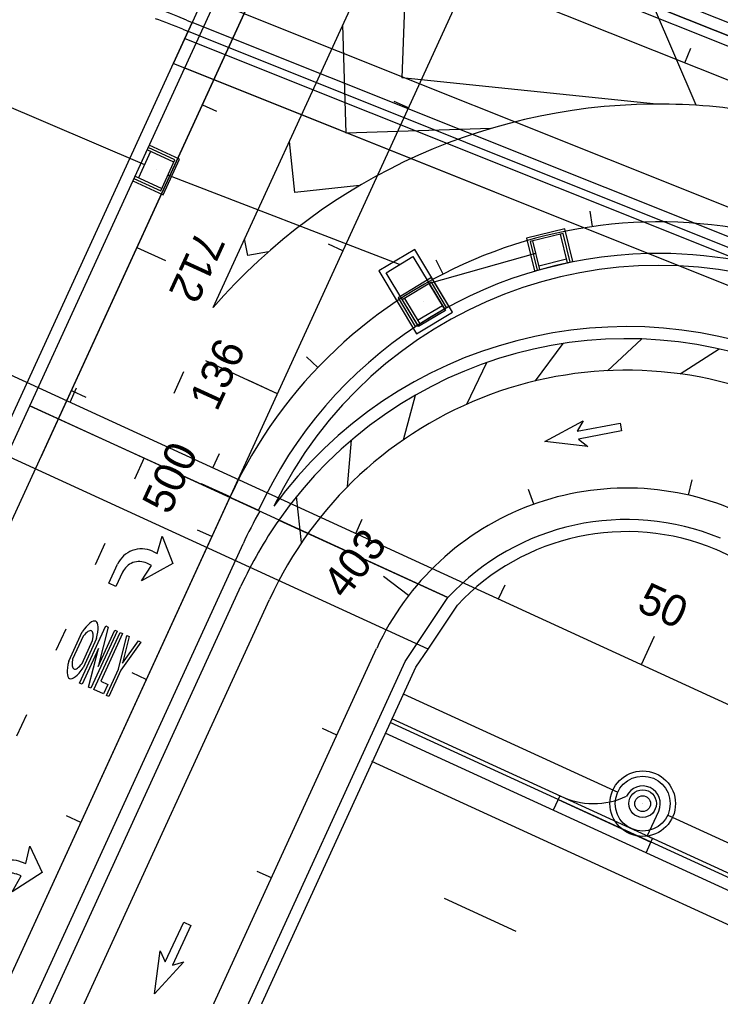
# Model space of a CAD drawing. Extents: x 468143 to 491361, y 1438528 to 1468730.
# Drawn here: x 487920.8 to 488010, y 1467075.2 to 1467199.5 of the extents above; entities that cross this region are included whole.
import ezdxf

# ---------------------------------------------------------------- set-up
doc = ezdxf.new("R2010")
doc.units = 0
doc.layers.add('Default', color=7, linetype='Continuous')
doc.layers.add('Xreference_dp', color=7, linetype='Continuous')

# ---------------------------------------------------------------- blocks, each defined once
blk = doc.blocks.new('POINT_DISPLAY')
at = {"layer": 'Default'}
blk.add_line((0, 0), (0, 0), dxfattribs=at)
blk = doc.blocks.new('InltCurb1_35')
at = {"layer": 'Default'}
for p, q in [((2.25, 2), (2.25, 5.5)), ((-10, 2), (-10, 0)), ((-10, 1.5), (3, 1.5)), ((3, 2), (2.25, 2)), ((3, 0), (3, 2))]:
    blk.add_line(p, q, dxfattribs=at)
for radius in [1.75, 1]:
    blk.add_circle((0, 5.5), radius, dxfattribs=at)
for centre, radius, start, end in [((0, 5.5), 2.25, 0, 180), ((-9.85, 12), 10, 269.1432, 319.4677)]:
    blk.add_arc(centre, radius, start, end, dxfattribs=at)
for p in [(0, 7.75), (-1.22, 6.76), (-0.66, 7.12), (0, 7.25), (0, 7.25), (0.7, 7.1), (1.26, 6.72), (-1.75, 5.5), (-1.75, 5.5), (-1.6, 6.2), (0, 5.5), (0, 5.5), (1.62, 6.16), (1.75, 5.5), (1.75, 5.5), (-1.62, 4.84), (-1.26, 4.28), (-0.7, 3.9), (0, 3.75), (0, 3.75), (0.66, 3.88), (1.22, 4.24), (1.6, 4.8), (0, 0), (0, 0)]:
    blk.add_blockref('POINT_DISPLAY', p, dxfattribs=at)
blk = doc.blocks.new('JBottom70Dia')
at = {"layer": 'Default'}
for radius in [4.17, 3.5, 3.5]:
    blk.add_circle((0, 0), radius, dxfattribs=at)
for p in [(-2.44, 2.51), (-1.32, 3.24), (0, 3.5), (0, 3.5), (0, 3.5), (1.41, 3.2), (-3.2, 1.41), (2.51, 2.44), (3.24, 1.32), (-3.5, 0), (-3.5, 0), (0, 0), (0, 0), (0, 0), (3.5, 0), (3.5, 0), (-3.24, -1.32), (-2.51, -2.44), (3.2, -1.41), (-1.41, -3.2), (0, -3.5), (0, -3.5), (0, -3.5), (1.32, -3.24), (2.44, -2.51)]:
    blk.add_blockref('POINT_DISPLAY', p, dxfattribs=at)
blk = doc.blocks.new('JBottom40x80_8')
at = {"layer": 'Default'}
for p, q in [((2.67, 4.67), (-2.67, 4.67)), ((-2.67, 4.67), (-2.67, -4.67)), ((-2, -4), (-2, 4)), ((-2, 4), (2, 4)), ((2, 4), (2, -4)), ((2.67, -4.67), (2.67, 4.67)), ((-2.67, -4.67), (2.67, -4.67)), ((2, -4), (-2, -4))]:
    blk.add_line(p, q, dxfattribs=at)
for p in [(-2, 4), (0, 4), (0, 4), (0, 4), (2, 4), (0, 0), (0, 0), (0, 0), (-2, 0), (-2, 0), (2, 0), (2, 0), (-2, -4), (0, -4), (0, -4), (0, -4), (2, -4)]:
    blk.add_blockref('POINT_DISPLAY', p, dxfattribs=at)
blk = doc.blocks.new('DAMerge_2')
at = {"layer": 'Default'}
blk.add_lwpolyline([(0.71, -4.09), (0, -3.39), (3.95, 0.56), (2.42, 0.68), (7.31, 3.21), (4.77, -1.68), (4.66, -0.15), (0.71, -4.09)], dxfattribs=at)
blk = doc.blocks.new('DALeftTurn_4_1')
at = {"layer": 'Default'}
for points in [[(5.67, 3.17), (2, 0.5), (4.33, 0.83), (4.33, 0.17)], [(6, 0.17), (6, 0.83), (8.25, 0.5), (5.67, 3.17)], [(2, -2.17), (0, -2.17), (0, -3.17), (2.67, -3.17)]]:
    blk.add_lwpolyline(points, dxfattribs=at)
for centre, radius in [((2, 0.17), 2.33), ((2.67, 0.17), 3.33)]:
    blk.add_arc(centre, radius, 270, 0, dxfattribs=at)
blk = doc.blocks.new('BikeONLY_3')
at = {"layer": 'Default'}
for p, q in [((0.97, 1.833), (3.03, 1.833)), ((2.8, 1.667), (1.2, 1.667)), ((3.03, 0.833), (0.97, 0.833)), ((1.2, 1), (2.8, 1))]:
    blk.add_line(p, q, dxfattribs=at)
for points in [[(0, -0.167), (0, 0), (2.5, 0.458), (0, 0.458), (0, 0.625), (4, 0.625), (4, 0.458), (1.45, 0), (4, 0), (4, -0.167), (0, -0.167)], [(0, -1.042), (0, -0.375), (4, -0.375), (4, -0.542), (0.667, -0.542), (0.667, -1.042), (0, -1.042)], [(4, -1.833), (1.833, -1.417), (0, -1.417), (0, -1.25), (1.833, -1.25), (4, -0.833), (4, -1.003), (2.283, -1.333), (4, -1.664), (4, -1.833)]]:
    blk.add_lwpolyline(points, dxfattribs=at)
for major_axis, ratio, start_param, end_param in [((2, 0), 0.291667, 2.111896, 4.171289), ((1.333, 0), 0.3125, 2.214297, 4.068888), ((1.333, 0), 0.3125, 5.35589, 7.210481), ((2, 0), 0.291667, 5.253489, 7.312882)]:
    blk.add_ellipse((2, 1.333), major_axis=major_axis, ratio=ratio, start_param=start_param, end_param=end_param, dxfattribs=at)
blk = doc.blocks.new('DARightTurn_4')
at = {"layer": 'Default'}
for points in [[(2, 2.17), (0, 2.17), (0, 3.17), (2.67, 3.17)], [(5.67, -3.17), (2, -0.5), (4.33, -0.83), (4.33, -0.17)], [(6, -0.17), (6, -0.83), (8.25, -0.5), (5.67, -3.17)]]:
    blk.add_lwpolyline(points, dxfattribs=at)
for centre, radius in [((2.67, -0.17), 3.33), ((2, -0.17), 2.33)]:
    blk.add_arc(centre, radius, 360, 90, dxfattribs=at)
blk = doc.blocks.new('DAMerge_6')
at = {"layer": 'Default'}
blk.add_lwpolyline([(0.71, -4.09), (0, -3.39), (3.95, 0.56), (2.42, 0.68), (7.31, 3.21), (4.77, -1.68), (4.66, -0.15), (0.71, -4.09)], dxfattribs=at)
blk = doc.blocks.new('DALeftTurn_5')
at = {"layer": 'Default'}
for points in [[(5.67, 3.17), (2, 0.5), (4.33, 0.83), (4.33, 0.17)], [(6, 0.17), (6, 0.83), (8.25, 0.5), (5.67, 3.17)], [(2, -2.17), (0, -2.17), (0, -3.17), (2.67, -3.17)]]:
    blk.add_lwpolyline(points, dxfattribs=at)
for centre, radius in [((2, 0.17), 2.33), ((2.67, 0.17), 3.33)]:
    blk.add_arc(centre, radius, 270, 0, dxfattribs=at)

msp = doc.modelspace()

# ---------------------------------------------------------------- linework, layer by layer
at = {"layer": 'Xreference_dp'}
for p, q in [((487372.29, 1467405.61), (488386.67, 1466939.92)), ((487859.77, 1466947.15), (487993.45, 1467238.69)), ((487859.77, 1466947.15), (487993.45, 1467238.69)), ((487965.18, 1467234.63), (487923.5, 1467143.73)), ((487945.48, 1467162.86), (487976.83, 1467231.24)), ((487856.07, 1466996.67), (487960.96, 1467225.43)), ((487940.43, 1467193.93), (487954.61, 1467224.87)), ((487941.86, 1467193.36), (487956.05, 1467224.3)), ((488054.01, 1467178.92), (487952.21, 1467219.64)), ((487970.43, 1467217.28), (487969.51, 1467192.12)), ((487948.97, 1467216.63), (488191.23, 1467119.72)), ((487936.77, 1467181.05), (487859.2, 1467214.13)), ((488074.17, 1467173.86), (487977.62, 1467212.48)), ((488073.59, 1467172.43), (487975.55, 1467211.65)), ((487977.21, 1467210.99), (488073.48, 1467172.48)), ((487943.4, 1467202.7), (488185.65, 1467105.79)), ((488006.95, 1467188.61), (488001.53, 1467201.26)), ((487941.99, 1467197.34), (487942.83, 1467199.16)), ((487942.1, 1467199.46), (487942.83, 1467199.16)), ((488045.62, 1467158.04), (487942.83, 1467199.16)), ((487917.83, 1467144.65), (487942.3, 1467198.03)), ((487941.63, 1467198.29), (487942.36, 1467198)), ((487942.3, 1467198.03), (488042.37, 1467157.99)), ((487941.89, 1467197.12), (488041.54, 1467157.25)), ((488005.53, 1467194), (488006.28, 1467195.86)), ((487940.43, 1467193.93), (488040.24, 1467154)), ((487922.15, 1467150.37), (487941.86, 1467193.36)), ((487941.86, 1467193.36), (488000.88, 1467169.75)), ((488001.92, 1467188.76), (487969.51, 1467192.12)), ((487944.11, 1467188.68), (487945.93, 1467187.85)), ((487970.33, 1467188.27), (487968.51, 1467189.1)), ((487937.35, 1467183.53), (487935.27, 1467178.99)), ((487941.22, 1467181.76), (487937.35, 1467183.53)), ((487937.53, 1467182.72), (487936, 1467179.39)), ((487940.48, 1467181.37), (487937.07, 1467182.93)), ((487940.62, 1467181.67), (487937.21, 1467183.23)), ((487938.82, 1467177.73), (487940.62, 1467181.67)), ((487939.13, 1467177.22), (487941.22, 1467181.76)), ((487935.27, 1467178.99), (487939.13, 1467177.22)), ((487935.41, 1467179.29), (487938.82, 1467177.73)), ((487935.55, 1467179.6), (487938.96, 1467178.03)), ((487969.2, 1467168.33), (487939.72, 1467179.7)), ((487993.75, 1467173.17), (487993.46, 1467175.15)), ((487990.23, 1467172.87), (487985.37, 1467171.68)), ((487991.24, 1467168.74), (487990.23, 1467172.87)), ((487985.37, 1467171.68), (487986.38, 1467167.55)), ((487990.02, 1467172.3), (487985.81, 1467171.27)), ((487985.81, 1467171.27), (487986.71, 1467167.63)), ((487986.14, 1467171.35), (487987.03, 1467167.71)), ((487990.59, 1467168.58), (487989.7, 1467172.22)), ((487990.92, 1467168.66), (487990.02, 1467172.3)), ((487935.78, 1467170.5), (487939.41, 1467168.84)), ((487961.99, 1467170.09), (487960.17, 1467170.92)), ((487986.52, 1467169.77), (487972.98, 1467165.93)), ((487986.52, 1467169.77), (487972.98, 1467165.93)), ((487974.77, 1467167.14), (487973.86, 1467168.92)), ((487986.38, 1467167.55), (487991.24, 1467168.74)), ((487986.91, 1467168.19), (487990.47, 1467169.07)), ((487973.29, 1467166.7), (487969.01, 1467164.12)), ((487973.26, 1467166.1), (487969.55, 1467163.87)), ((487975.19, 1467162.88), (487973.26, 1467166.1)), ((487975.48, 1467163.06), (487973.29, 1467166.7)), ((487974.91, 1467162.71), (487972.98, 1467165.93)), ((487969.01, 1467164.12), (487971.19, 1467160.48)), ((487969.55, 1467163.87), (487971.48, 1467160.65)), ((487969.83, 1467164.04), (487971.77, 1467160.82)), ((487971.19, 1467160.48), (487975.48, 1467163.06)), ((487971.51, 1467161.25), (487974.65, 1467163.14)), ((487995.66, 1467154.84), (487999.98, 1467158.87)), ((487986.51, 1467153.54), (487990.01, 1467158.29)), ((488004.9, 1467154.44), (488009.89, 1467157.6)), ((487958.81, 1467155.24), (487957.37, 1467156.62)), ((487953.66, 1467151.91), (487944.57, 1467156.08)), ((487977.75, 1467150.57), (487980.32, 1467155.89)), ((487941.72, 1467154.68), (487940.47, 1467151.95)), ((487927.27, 1467150.82), (487928.11, 1467152.64)), ((487953.66, 1467151.91), (487950.02, 1467153.58)), ((487927.44, 1467152.32), (487929.26, 1467151.49)), ((487969.69, 1467146.04), (487971.24, 1467151.74)), ((487849.18, 1466991.24), (487922.15, 1467150.37)), ((487975.36, 1467125.97), (487922.15, 1467150.37)), ((487922.15, 1467150.37), (487951.27, 1467137.1)), ((487962.6, 1467140.11), (487963.07, 1467145.99)), ((487972.84, 1467119.42), (487917.83, 1467144.65)), ((487936.72, 1467143.77), (487935.47, 1467141.04)), ((487945.45, 1467142.48), (487946.28, 1467144.3)), ((487947.63, 1467138.77), (487943.99, 1467140.44)), ((488005.98, 1467139.01), (488006.43, 1467140.95)), ((487859.77, 1466947.15), (487947.63, 1467138.77)), ((487956.73, 1467132.97), (487956.1, 1467138.84)), ((487986.29, 1467137.85), (487985.61, 1467139.73)), ((487953.84, 1467135.83), (487975.36, 1467125.97)), ((487963.63, 1467134.13), (487964.46, 1467135.95)), ((487945.32, 1467133.73), (487943.5, 1467134.56)), ((487878.29, 1466977.96), (487949.29, 1467132.79)), ((487931.72, 1467132.86), (487930.47, 1467130.14)), ((488009.46, 1467132.11), (488535.31, 1466889.3)), ((487970.35, 1467126.22), (487967.18, 1467128.65)), ((487981.8, 1467125.79), (487982.64, 1467127.61)), ((487880.11, 1466977.12), (487949.02, 1467127.41)), ((487883.23, 1466974.33), (487952.66, 1467125.74)), ((487969.93, 1467117.82), (487975.36, 1467125.97)), ((487972.84, 1467119.42), (487976.58, 1467125.01)), ((487926.72, 1467121.96), (487925.47, 1467119.23)), ((487999.98, 1467117.44), (488001.65, 1467121.08)), ((487896.86, 1466968.07), (487966.29, 1467119.49)), ((487896.86, 1466968.07), (487966.29, 1467119.49)), ((487971.29, 1467117.1), (487972.84, 1467119.42)), ((487903.94, 1466973.9), (487969.93, 1467117.82)), ((487905.34, 1466973.26), (487971.29, 1467117.1)), ((487936.98, 1467115.55), (487935.17, 1467116.39)), ((487969.68, 1467113.72), (487996.97, 1467101.21)), ((487921.72, 1467111.05), (487920.47, 1467108.32)), ((488379.42, 1466921.99), (487968.21, 1467110.55)), ((487961.24, 1467108.47), (487959.42, 1467109.3)), ((488379.21, 1466921.54), (487968, 1467110.09)), ((488378.58, 1466920.18), (487967.36, 1467108.73)), ((488376.92, 1466916.54), (487965.68, 1467105.11)), ((487928.65, 1467097.37), (487926.83, 1467098.21)), ((488003.33, 1467098.29), (488087.86, 1467059.53)), ((487952.9, 1467090.29), (487951.08, 1467091.12)), ((487984.03, 1467083.49), (487974.94, 1467087.66))]:
    msp.add_line(p, q, dxfattribs=at)
for points in [[(487980.83, 1467185.66), (487962.43, 1467185.05), (487961.97, 1467198.84)], [(487964.11, 1467178.39), (487955.88, 1467177.5), (487955.18, 1467184.02)], [(487952.53, 1467169.98), (487949.89, 1467169.49), (487949.49, 1467171.63)]]:
    msp.add_lwpolyline(points, dxfattribs=at)
for centre, radius, start, end in [((487523.34, 1466152.69), 1127.42, 68.1961, 69.14997), ((487416.74, 1465829.61), 1465.88, 69.01753, 69.16453), ((488002.17, 1467113.76), 75, 88.9711, 139.1069), ((488002.17, 1467113.76), 75, 68.1341, 88.9711), ((488002.17, 1467113.76), 60, 68.1961, 155.3671), ((488002.17, 1467113.76), 60, 68.1961, 155.3671), ((488002.17, 1467113.76), 56, 91.3222, 155.3671), ((488002.17, 1467113.76), 56, 68.1961, 91.3222), ((488002.17, 1467113.76), 54.46, 68.1961, 154.058), ((487998.11, 1467104.9), 55.54, 65.2153, 143.9544), ((487998.11, 1467104.9), 54, 65.2153, 145.0537), ((487998.11, 1467104.9), 50, 65.2153, 155.3671), ((487998.11, 1467104.9), 50, 65.2153, 155.3671), ((487998.11, 1467104.9), 35, 65.2153, 155.3671), ((487998.11, 1467104.9), 35, 65.2153, 155.3671), ((488000.19, 1467109.45), 56, 150.5858, 155.3671), ((487998.11, 1467104.9), 54, 145.0537, 155.3671), ((487998.11, 1467104.9), 31, 67.3625, 137.1956), ((487998.11, 1467104.9), 29.46, 67.3625, 136.9606)]:
    msp.add_arc(centre, radius, start, end, dxfattribs=at)

# ---------------------------------------------------------------- block references
for name, p, rotation in [('POINT_DISPLAY', (487937.53, 1467182.72), 65.36711903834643), ('POINT_DISPLAY', (487936.31, 1467181.26), 65.36711903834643), ('POINT_DISPLAY', (487936.31, 1467181.26), 65.36711903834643), ('POINT_DISPLAY', (487936.77, 1467181.05), 65.36711903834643), ('POINT_DISPLAY', (487936.77, 1467181.05), 65.36711903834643), ('POINT_DISPLAY', (487939.01, 1467182.04), 65.36711903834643), ('POINT_DISPLAY', (487939.01, 1467182.04), 65.36711903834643), ('POINT_DISPLAY', (487940.48, 1467181.37), 65.36711903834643), ('POINT_DISPLAY', (487938.24, 1467180.38), 65.36711903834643), ('POINT_DISPLAY', (487938.24, 1467180.38), 65.36711903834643), ('POINT_DISPLAY', (487936, 1467179.39), 65.36711903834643), ('POINT_DISPLAY', (487937.48, 1467178.71), 65.36711903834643), ('POINT_DISPLAY', (487937.48, 1467178.71), 65.36711903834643), ('POINT_DISPLAY', (487939.72, 1467179.7), 65.36711903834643), ('POINT_DISPLAY', (487939.72, 1467179.7), 65.36711903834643), ('POINT_DISPLAY', (487940.17, 1467179.49), 65.36711903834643), ('POINT_DISPLAY', (487938.96, 1467178.03), 65.36711903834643), ('POINT_DISPLAY', (487986.14, 1467171.35), -166.19908272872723), ('POINT_DISPLAY', (487987.8, 1467172.27), -166.19908272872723), ('POINT_DISPLAY', (487987.92, 1467171.79), -166.19908272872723), ('POINT_DISPLAY', (487987.92, 1467171.79), -166.19908272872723), ('POINT_DISPLAY', (487989.7, 1467172.22), -166.19908272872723), ('JBottom40x80_8', (487971.26, 1467164.9), -149.01034887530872), ('POINT_DISPLAY', (487988.3, 1467170.21), -166.19908272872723), ('POINT_DISPLAY', (487988.3, 1467170.21), -166.19908272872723), ('POINT_DISPLAY', (487990.08, 1467170.65), -166.19908272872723), ('POINT_DISPLAY', (487990.08, 1467170.65), -166.19908272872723), ('POINT_DISPLAY', (487986.52, 1467169.77), -166.19908272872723), ('POINT_DISPLAY', (487986.52, 1467169.77), -166.19908272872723), ('POINT_DISPLAY', (487988.69, 1467168.63), -166.19908272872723), ('POINT_DISPLAY', (487988.69, 1467168.63), -166.19908272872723), ('POINT_DISPLAY', (487990.47, 1467169.07), -166.19908272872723), ('POINT_DISPLAY', (487986.91, 1467168.19), -166.19908272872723), ('POINT_DISPLAY', (487988.81, 1467168.15), -166.19908272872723), ('POINT_DISPLAY', (487988.81, 1467168.15), -166.19908272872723), ('POINT_DISPLAY', (487971.15, 1467165.41), -149.01034887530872), ('POINT_DISPLAY', (487971.41, 1467164.98), -149.01034887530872), ('POINT_DISPLAY', (487971.41, 1467164.98), -149.01034887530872), ('POINT_DISPLAY', (487972.98, 1467165.93), -149.01034887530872), ('POINT_DISPLAY', (487969.83, 1467164.04), -149.01034887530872), ('POINT_DISPLAY', (487973.81, 1467164.53), -149.01034887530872), ('POINT_DISPLAY', (487973.81, 1467164.53), -149.01034887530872), ('POINT_DISPLAY', (487970.67, 1467162.65), -149.01034887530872), ('POINT_DISPLAY', (487970.67, 1467162.65), -149.01034887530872), ('POINT_DISPLAY', (487972.24, 1467163.59), -149.01034887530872), ('POINT_DISPLAY', (487972.24, 1467163.59), -149.01034887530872), ('POINT_DISPLAY', (487974.65, 1467163.14), -149.01034887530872), ('POINT_DISPLAY', (487971.51, 1467161.25), -149.01034887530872), ('POINT_DISPLAY', (487973.08, 1467162.2), -149.01034887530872), ('POINT_DISPLAY', (487973.08, 1467162.2), -149.01034887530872), ('POINT_DISPLAY', (487973.34, 1467161.77), -149.01034887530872), ('POINT_DISPLAY', (487973.34, 1467161.77), -149.01034887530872), ('DAMerge_2', (487995.56, 1467144.39), 145.8245338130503), ('DAMerge_6', (487995.56, 1467144.39), 145.8245338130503), ('DARightTurn_4', (487935.09, 1467126.48), 65.36711924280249), ('InltCurb1_35', (487997.85, 1467094.75), -24.632880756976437), ('JBottom70Dia', (488000.15, 1467099.75), 75.32156597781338), ('DAMerge_2', (487943.81, 1467081.07), -160.01330064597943), ('DAMerge_6', (487943.81, 1467081.07), -160.01330064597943)]:
    msp.add_blockref(name, p, dxfattribs=dict(at, rotation=rotation))
at = {"layer": 'Xreference_dp', "xscale": 2, "yscale": 2, "rotation": 65.36711924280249}
msp.add_blockref('BikeONLY_3', (487929.63, 1467114.57), dxfattribs=at)
at = {"layer": 'Xreference_dp', "yscale": -1, "rotation": 68.82662784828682}
for name in ['DALeftTurn_4_1', 'DALeftTurn_5']:
    msp.add_blockref(name, (487918.71, 1467086.83), dxfattribs=at)

# ---------------------------------------------------------------- texts
at = {"layer": 'Xreference_dp'}
for s, rotation, p in [('712', 245.3671, (487943.48, 1467172.9)), ('136', 65.3671, (487945.96, 1467149.52)), ('500', 65.3671, (487939.93, 1467136.37)), ('403', 52.4806, (487962.31, 1467125.6)), ('50', 335.3408, (487999.22, 1467124.4))]:
    msp.add_text(s, height=4, rotation=rotation, dxfattribs=at).set_placement(p)

doc.saveas('drawing.dxf')
